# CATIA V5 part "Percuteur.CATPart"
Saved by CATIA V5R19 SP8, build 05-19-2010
Part number: Percuteur
Bounding box of the stored display mesh (mm): x -70 to 5, y -2.965 to 2.965, z -2.83 to 7.58
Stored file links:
  E:\Catia parts\GLOCK\Ensemble culasse\Percuteur.CATPart
  E:\Catia parts\GLOCK\Ensemble culasse\piece percuteur X.CATPart
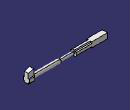
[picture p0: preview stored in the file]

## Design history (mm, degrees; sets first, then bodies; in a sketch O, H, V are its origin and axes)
Body1 (main body)
  Solid1: solid without history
